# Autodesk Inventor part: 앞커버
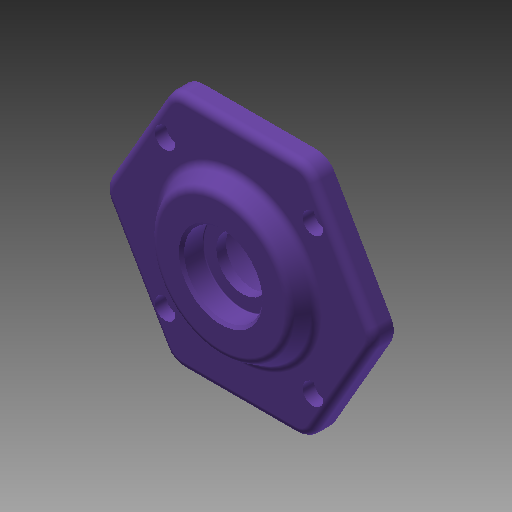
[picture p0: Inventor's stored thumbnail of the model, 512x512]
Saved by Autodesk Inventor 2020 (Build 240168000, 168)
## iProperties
Created: 2013-02
Part Number: 앞커버
Document SubType Name: Modeling
Density: 1 g/cm^3
Material: 일반
Appearance: 보라색
Author: 한국산업디자인학원[gmhk.co.kr]
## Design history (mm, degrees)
sketch "스케치1" dims "d37" = 105
  geometry: L1 (28.559, 41.466)-(50.191, 4); L2 (50.191, -4)-(28.559, -41.466); L3 (21.631, -45.466)-(-21.631, -45.466); L4 (-28.559, -41.466)-(-50.191, -4); L5 (-50.191, 4)-(-28.559, 41.466); L6 (-21.631, 45.466)-(21.631, 45.466); C1 r 30 at (0, 0); A1 r 8 centre (-43.262, 0) between (-50.191, 4) and (-50.191, -4); A2 r 8 centre (-21.631, 37.466) between (-21.631, 45.466) and (-28.559, 41.466); A3 r 8 centre (21.631, 37.466) between (28.559, 41.466) and (21.631, 45.466); A4 r 8 centre (43.262, 0) between (50.191, -4) and (50.191, 4); A5 r 8 centre (21.631, -37.466) between (21.631, -45.466) and (28.559, -41.466); A6 r 8 centre (-21.631, -37.466) between (-28.559, -41.466) and (-21.631, -45.466); 9 further points
  constraints: 12 end point, 12 point on circle, 12 point on line, 12 tangent, 7 centre point, 5 equal radius, 3 coincident, 1 horizontal, 16 other
  dimensions: "d40" = 8 radius of A1; "d41" = 60 diameter of C1
extrude "돌출1" new body sketch "스케치1" distance "d0" = 8; taper "d1" = 0 deg
sketch "스케치2"
  geometry: C1 r 30 at (0, 0); 1 further point
  constraints: 1 centre point, 1 coincident
  dimensions: "d2" = 60 diameter of C1
extrude "돌출2" join sketch "스케치2" distance "d3" = 7; taper "d4" = -30 deg
hole "구멍1" diameter "d7" = 20; stored, may be unused: countersink angle "d11" = 90 deg, drill point angle "d13" = 118 deg; dims "d8" = 6, "d9" = 30, "d10" = 8.3, "d12" = 20, "d52" = 10, "d53" = 10
sketch "스케치3"
  geometry: L1 (-28.284, 28.284)-(0, 0); L2 (0, 0)-(0, 40); L3 (0, 0)-(28.284, 28.284); L4 (0, 0)-(28.284, -28.284); L5 (0, 0)-(-28.284, -28.284); C1 r 1.621 at (28.284, 28.284); C2 r 1.621 at (-28.284, 28.284); C3 r 1.621 at (-28.284, -28.284); C4 r 1.621 at (28.284, -28.284); C5 r 10 at (0, 0) reference; A1 r 40 centre (0, 0) between (28.284, 28.284) and (-28.284, 28.284)
  constraints: 10 end point, 5 centre point, 3 perpendicular, 3 point on circle, 1 coincident, 1 vertical
  dimensions: "d48" = 80 diameter of A1; "d50" = 45 deg angle of L2 L1
hole "구멍2" sketch "스케치3" at (28.284, 28.284), (28.284, -28.284), (-28.284, -28.284), (-28.284, 28.284) diameter "d14" = 4.5; stored, may be unused: countersink angle "d18" = 90 deg, drill point angle "d20" = 118 deg; dims "d15" = 6, "d16" = 8, "d17" = 4.4, "d19" = 20
extrude "돌출3" join sketch "스케치1" distance "d21" = 12; taper "d22" = 0 deg
hole "구멍3" diameter "d25" = 30; stored, may be unused: countersink angle "d29" = 90 deg, drill point angle "d31" = 0 deg; dims "d26" = 6, "d27" = 40, "d28" = 12, "d30" = 15, "d42" = 10, "d43" = 10
fillet "모깎기1" dims "d32" = 3, "d33" = 0.3
chamfer "모따기1" distance "d34" = 1; stored, may be unused: second distance "d35" = 2, angle "d36" = 45 deg
chamfer "모따기2" distance "d44" = 1; stored, may be unused: second distance "d45" = 2, angle "d46" = 45 deg
fillet "모깎기2" dims "d47" = 3
fillet "모깎기3" dims "d54" = 0.6
node "솔리드1"
